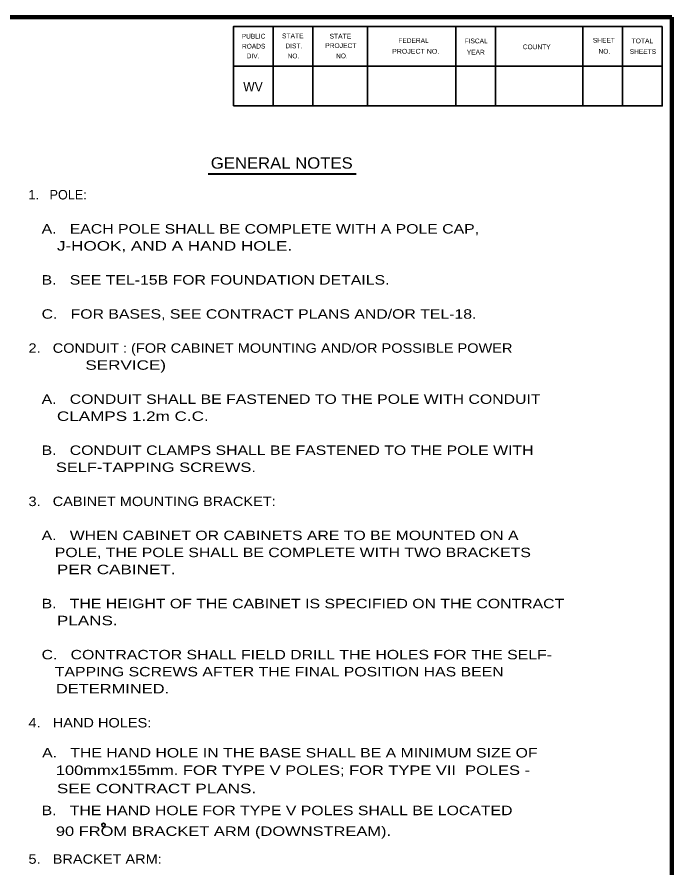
# Model space of a CAD drawing. Extents: x -20 to 693, y -19 to 435.
# Drawn here: x 513.2 to 687.7, y 202.7 to 429.4 of the extents above; entities that cross this region are included whole.
import ezdxf

# ---------------------------------------------------------------- set-up
doc = ezdxf.new("R2010")
doc.units = 0
doc.layers.add('1', color=7, linetype='Continuous', lineweight=53)
doc.layers.add('61', color=7, linetype='Continuous', lineweight=35)

msp = doc.modelspace()

# ---------------------------------------------------------------- linework, layer by layer
at = {"layer": '1', "lineweight": 158}
msp.add_line((687.723, -9.063), (687.723, 429.353), dxfattribs=at)
at = {"layer": '1', "lineweight": 13}
msp.add_line((687.723, -9.063), (687.723, 429.353), dxfattribs=at)
at = {"layer": '1', "lineweight": 40}
msp.add_line((564.124, 387.587), (603.563, 387.587), dxfattribs=at)
at = {"layer": '1', "lineweight": 158}
msp.add_lwpolyline([(687.723, 429.353), (27.973, 429.27), (28.056, -9.063)], dxfattribs=at)
at = {"layer": '1', "lineweight": 35}
msp.add_circle((536.238, 214.174), 0.481, dxfattribs=at)
at = {"layer": '61'}
for p, q in [((581.473, 426.853), (581.473, 405.687)), ((592.056, 426.853), (592.056, 405.687)), ((606.556, 426.853), (606.556, 405.687)), ((630.14, 426.853), (630.14, 405.687)), ((640.723, 426.853), (640.723, 405.687)), ((663.973, 426.853), (663.973, 405.687)), ((674.556, 426.853), (674.556, 405.687)), ((685.14, 416.27), (570.89, 416.27))]:
    msp.add_line(p, q, dxfattribs=at)
for points in [[(685.14, 426.853), (570.89, 426.853), (570.89, 405.687)], [(685.14, 426.853), (685.14, 405.687), (570.89, 405.687)]]:
    msp.add_lwpolyline(points, dxfattribs=at)

# ---------------------------------------------------------------- texts
at = {"layer": '1'}
for s, height, width, p in [('WV', 2.54, 0.95, (573.473, 409.52)), ('GENERAL NOTES', 3.024, 1.1, (564.823, 388.967)), ('   A.   EACH POLE SHALL BE COMPLETE WITH A POLE CAP,', 2.52, 1.25, (516.243, 371.687)), ('      J-HOOK, AND A HAND HOLE.', 2.52, 1.35, (516.243, 367.147)), ('   B.   SEE TEL-15B FOR FOUNDATION DETAILS.', 2.52, 1.25, (516.243, 358.087)), ('   C.   FOR BASES, SEE CONTRACT PLANS AND/OR TEL-18.', 2.52, 1.25, (516.243, 349.007)), ('2.   CONDUIT : (FOR CABINET MOUNTING AND/OR POSSIBLE POWER', 2.52, 1.15, (516.243, 339.927)), ('            SERVICE)', 2.52, 1.35, (516.243, 335.407)), ('   A.   CONDUIT SHALL BE FASTENED TO THE POLE WITH CONDUIT', 2.52, 1.25, (516.243, 326.327)), ('      CLAMPS 1.2m C.C.', 2.52, 1.35, (516.243, 321.787)), ('   B.   CONDUIT CLAMPS SHALL BE FASTENED TO THE POLE WITH', 2.52, 1.25, (516.243, 312.727)), ('      SELF-TAPPING SCREWS.', 2.52, 1.3, (516.243, 308.187)), ('3.   CABINET MOUNTING BRACKET:', 2.52, 1.15, (516.243, 299.107)), ('   A.   WHEN CABINET OR CABINETS ARE TO BE MOUNTED ON A', 2.52, 1.25, (516.243, 290.047)), ('      POLE, THE POLE SHALL BE COMPLETE WITH TWO BRACKETS', 2.52, 1.25, (516.243, 285.507)), ('      PER CABINET.', 2.52, 1.35, (516.243, 280.967)), ('   B.   THE HEIGHT OF THE CABINET IS SPECIFIED ON THE CONTRACT', 2.52, 1.25, (516.243, 271.887)), ('      PLANS.', 2.52, 1.35, (516.243, 267.367)), ('   C.   CONTRACTOR SHALL FIELD DRILL THE HOLES FOR THE SELF-', 2.52, 1.25, (516.243, 258.287)), ('      TAPPING SCREWS AFTER THE FINAL POSITION HAS BEEN', 2.52, 1.25, (516.243, 253.747)), ('      DETERMINED.', 2.52, 1.3, (516.243, 249.207)), ('4.   HAND HOLES:', 2.52, 1.15, (516.243, 240.147)), ('   A.   THE HAND HOLE IN THE BASE SHALL BE A MINIMUM SIZE OF', 2.52, 1.25, (516.379, 232.153)), ('      100mmx155mm. FOR TYPE V POLES; FOR TYPE VII  POLES -', 2.52, 1.3, (516.243, 227.504)), ('      SEE CONTRACT PLANS.', 2.52, 1.35, (516.243, 222.637)), ('   B.   THE HAND HOLE FOR TYPE V POLES SHALL BE LOCATED', 2.52, 1.25, (516.243, 216.787)), ('      90 FROM BRACKET ARM (DOWNSTREAM).', 2.52, 1.3, (516.243, 211.267)), ('5.   BRACKET ARM:', 2.52, 1.15, (516.243, 203.847))]:
    msp.add_text(s, height=height, dxfattribs=dict(at, width=width)).set_placement(p)
msp.add_text('1.   POLE:', height=2.52, dxfattribs=at).set_placement((516.243, 380.767))
at = {"layer": '61'}
for s, height, rotation, p in [('PUBLIC', 1.271, 0.033, (573.056, 423.603)), ('SHEET', 1.271, 0.059, (666.64, 422.52)), ('ROADS', 1.27, 0.124, (573.14, 420.937)), ('DIST.', 1.27, 0.056, (584.723, 421.02)), ('FEDERAL', 1.27, 0.007, (614.806, 422.437)), ('FISCAL', 1.271, 359.942, (632.473, 422.353)), ('COUNTY', 1.269, 0.069, (647.973, 420.77)), ('DIV.', 1.27, 359.932, (574.39, 418.353)), ('YEAR', 1.27, 0.105, (633.056, 419.353)), ('SHEETS', 1.269, 359.959, (676.473, 419.52))]:
    msp.add_text(s, height=height, rotation=rotation, dxfattribs=at).set_placement(p)
for s, height, rotation, width, p in [('STATE', 1.271, 0.059, 1.05, (583.806, 423.687)), ('STATE', 1.271, 0.059, 1.05, (596.473, 423.603)), ('PROJECT', 1.27, 359.908, 1.05, (595.306, 421.103)), ('TOTAL', 1.27, 359.926, 1.05, (676.973, 422.353)), ('NO.', 1.27, 359.852, 0.9, (585.306, 418.353)), ('NO.', 1.271, 0.225, 0.9, (598.223, 418.353)), ('PROJECT NO.', 1.27, 359.922, 1.1, (613.14, 419.603)), ('NO.', 1.27, 359.852, 0.9, (668.14, 419.603))]:
    msp.add_text(s, height=height, rotation=rotation, dxfattribs=dict(at, width=width)).set_placement(p)

doc.saveas('drawing.dxf')
